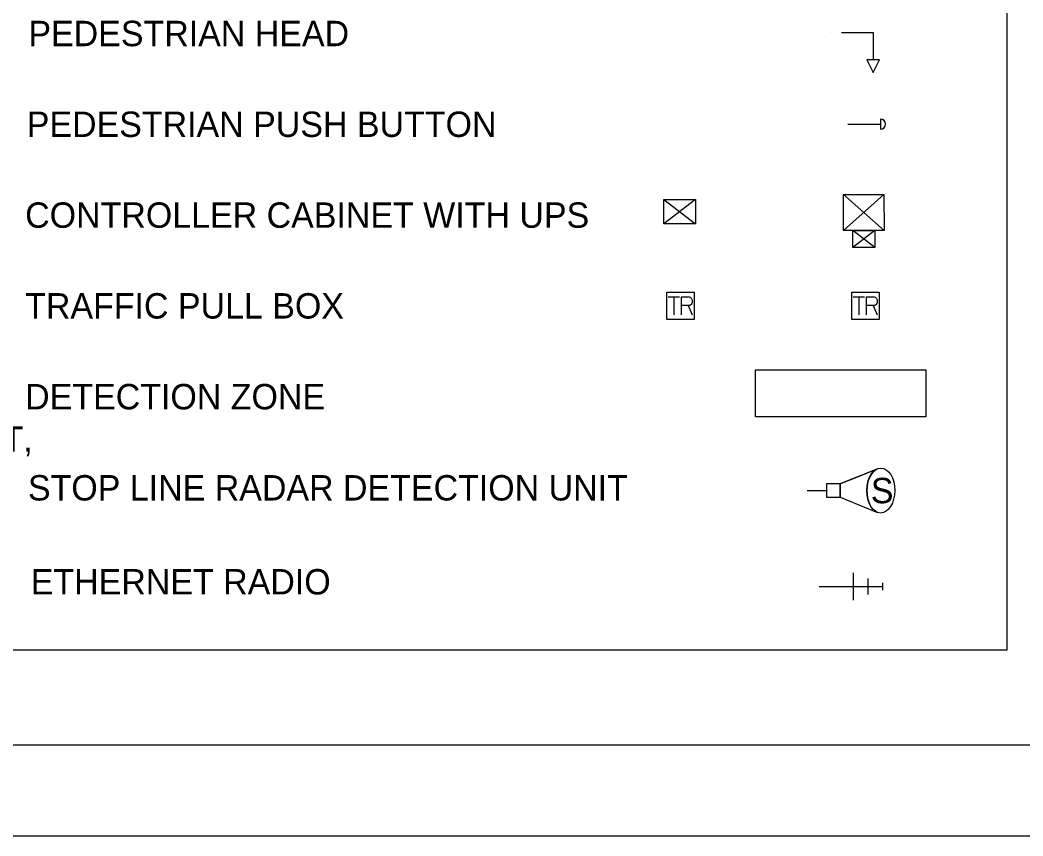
# Model space of a CAD drawing. Extents: x -32.9 to 34, y 0 to 22.3.
# Drawn here: x 25.25 to 30.78, y 0 to 4.5 of the extents above; entities that cross this region are included whole.
import ezdxf

# ---------------------------------------------------------------- set-up
doc = ezdxf.new("R2010")
doc.units = 0
for name, color, linetype in [('GE_P_Alignment', 7, 'Continuous'), ('GE_P_Driveway_CL', 7, 'Continuous'), ('PF_X_Ground_Line', 7, 'Continuous'), ('PV_P_Curb_Ramp', 7, 'Continuous'), ('PV_P_Saw_Cut_Line', 7, 'Continuous'), ('PV_P_Walk', 7, 'Continuous'), ('RW_P_Const_Limits', 7, 'Continuous'), ('SC_Scratch1', 7, 'Continuous')]:
    doc.layers.add(name, color=color, linetype=linetype)

msp = doc.modelspace()

# ---------------------------------------------------------------- linework, layer by layer
at = {"layer": 'GE_P_Alignment'}
msp.add_lwpolyline([(0, 0), (34, 0), (34, 22), (0, 22)], close=True, dxfattribs=at)
at = {"layer": 'GE_P_Driveway_CL'}
msp.add_line((29.7227, 4.4288), (29.7227, 4.4288), dxfattribs=at)
msp.add_lwpolyline([(29.7827, 4.4288), (29.9577, 4.4288), (29.9577, 4.2788)], dxfattribs=at)
msp.add_lwpolyline([(29.9927, 4.2788), (29.9227, 4.2788), (29.9577, 4.2088)], close=True, dxfattribs=at)
at = {"layer": 'PF_X_Ground_Line'}
for p, q in [((28.802, 3.5083), (28.977, 3.375)), ((28.977, 3.5083), (28.802, 3.375)), ((28.8946, 2.9224), (28.8946, 2.9224)), ((29.9147, 2.9224), (29.9147, 2.9224))]:
    msp.add_line(p, q, dxfattribs=at)
for points in [[(28.977, 3.375), (28.802, 3.375), (28.802, 3.5083), (28.977, 3.5083)], [(28.8196, 2.9974), (28.9696, 2.9974), (28.9696, 2.8474), (28.8196, 2.8474)], [(29.8397, 2.9974), (29.9897, 2.9974), (29.9897, 2.8474), (29.8397, 2.8474)], [(29.3076, 2.5696), (30.2471, 2.5696), (30.2471, 2.3098), (29.3076, 2.3098)], [(29.3076, 2.5696), (30.2471, 2.5696), (30.2471, 2.3098), (29.3076, 2.3098)]]:
    msp.add_lwpolyline(points, close=True, dxfattribs=at)
for points in [[(28.8268, 2.9724), (28.889, 2.9724)], [(28.8583, 2.9724), (28.8583, 2.8724)], [(28.9002, 2.8724), (28.9002, 2.9724), (28.938, 2.9724), (28.942, 2.9716), (28.9475, 2.97), (28.9498, 2.9684), (28.9522, 2.9669), (28.9554, 2.9629), (28.9577, 2.959), (28.9593, 2.9527), (28.9593, 2.9432), (28.9585, 2.9401), (28.9569, 2.9354), (28.9538, 2.9299), (28.9506, 2.9275), (28.9483, 2.9259), (28.9467, 2.9251), (28.9443, 2.9243), (28.9372, 2.9236), (28.9002, 2.9236)], [(29.8469, 2.9724), (29.9091, 2.9724)], [(29.8784, 2.9724), (29.8784, 2.8724)], [(29.9203, 2.8724), (29.9203, 2.9724), (29.9581, 2.9724), (29.962, 2.9716), (29.9675, 2.97), (29.9699, 2.9684), (29.9722, 2.9669), (29.9754, 2.9629), (29.9777, 2.959), (29.9793, 2.9527), (29.9793, 2.9432), (29.9785, 2.9401), (29.977, 2.9354), (29.9738, 2.9299), (29.9707, 2.9275), (29.9683, 2.9259), (29.9667, 2.9251), (29.9644, 2.9243), (29.9573, 2.9236), (29.9203, 2.9236)], [(28.9372, 2.9236), (28.9593, 2.8724)], [(29.9573, 2.9236), (29.9793, 2.8724)]]:
    msp.add_lwpolyline(points, dxfattribs=at)
at = {"layer": 'PV_P_Curb_Ramp'}
msp.add_lwpolyline([(1.5, 21.5), (33.5, 21.5), (33.5, 0.5), (1.5, 0.5)], close=True, dxfattribs=at)
at = {"layer": 'PV_P_Saw_Cut_Line'}
msp.add_lwpolyline([(25.1759, 8.2113), (25.1759, 1.0264), (30.6953, 1.0264), (30.6953, 7.4577), (30.6953, 8.2113)], close=True, dxfattribs=at)
at = {"layer": 'PV_P_Walk'}
for p, q in [((29.9974, 3.9522), (29.9974, 3.8962)), ((29.8174, 3.9242), (29.9974, 3.9242)), ((29.7746, 1.9419), (29.9804, 2.0245)), ((29.9804, 2.0245), (29.7746, 1.9419)), ((29.7746, 1.9419), (29.7746, 1.8669)), ((29.5935, 1.9044), (29.6996, 1.9044)), ((29.7746, 1.8669), (29.9803, 1.784)), ((29.7746, 1.8669), (29.9803, 1.784))]:
    msp.add_line(p, q, dxfattribs=at)
msp.add_lwpolyline([(29.6996, 1.9419), (29.6996, 1.8669), (29.7746, 1.8669), (29.7746, 1.9419)], close=True, dxfattribs=at)
msp.add_lwpolyline([(29.6996, 1.9419), (29.6996, 1.8669), (29.7746, 1.8669), (29.7746, 1.9419), (29.6996, 1.9419)], dxfattribs=at)
msp.add_arc((29.9974, 3.9242), 0.028, 270.0002, 89.9998, dxfattribs=at)
msp.add_ellipse((29.999, 1.9042), major_axis=(-0.0001, -0.1239), ratio=0.621318, dxfattribs=at)
msp.add_ellipse((29.999, 1.9042), major_axis=(-0.0001, -0.1239), ratio=0.621318, start_param=3.386213, end_param=6.038231, dxfattribs=at)
at = {"layer": 'RW_P_Const_Limits'}
for p, q in [((30.0173, 3.3381), (29.7925, 3.5362)), ((30.0165, 3.5371), (29.7933, 3.3371)), ((29.9661, 3.2448), (29.8449, 3.3374)), ((29.9657, 3.3379), (29.8453, 3.2443))]:
    msp.add_line(p, q, dxfattribs=at)
for points in [[(30.0165, 3.5371), (30.0173, 3.3381), (29.7933, 3.3371), (29.7925, 3.5362)], [(29.9657, 3.3379), (29.9661, 3.2448), (29.8453, 3.2443), (29.8449, 3.3374)]]:
    msp.add_lwpolyline(points, close=True, dxfattribs=at)
at = {"layer": 'SC_Scratch1'}
for p, q in [((29.8487, 1.3002), (29.8487, 1.4502)), ((29.9287, 1.3302), (29.9287, 1.4202)), ((30.0087, 1.3952), (30.0087, 1.3552)), ((29.6587, 1.3752), (30.0087, 1.3752))]:
    msp.add_line(p, q, dxfattribs=at)

# ---------------------------------------------------------------- texts
at = {"layer": 'PF_X_Ground_Line'}
for s, p in [('PEDESTRIAN HEAD', (25.2989, 4.354)), ('PEDESTRIAN PUSH BUTTON', (25.2899, 3.8535)), ('CONTROLLER CABINET WITH UPS', (25.281, 3.3529)), ('TRAFFIC PULL BOX ', (25.281, 2.8524)), ('DETECTION ZONE', (25.281, 2.3518)), ('STOP LINE RADAR DETECTION UNIT', (25.2964, 1.8493)), ('ETHERNET RADIO', (25.3119, 1.3313))]:
    msp.add_text(s, height=0.14, dxfattribs=at).set_placement(p)
at = {"layer": 'PV_P_Saw_Cut_Line'}
msp.add_text('A CALL THAT A TRAIN IS APPROACHING FROM THE EAST OR WEST,', height=0.14, dxfattribs=at).set_placement((19.1337, 2.118))
at = {"layer": 'PV_P_Walk'}
msp.add_text('S', height=0.14, dxfattribs=at).set_placement((29.9441, 1.8342))

doc.saveas('drawing.dxf')
